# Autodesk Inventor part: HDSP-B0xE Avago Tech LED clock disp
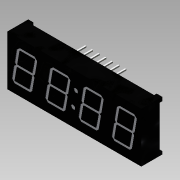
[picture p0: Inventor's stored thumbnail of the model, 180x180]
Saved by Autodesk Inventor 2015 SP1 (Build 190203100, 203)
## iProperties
Created: 2015-05
Part Number: HDSP-B0xE Avago Tech LED clock disp
Material: Thermoplastic Resin
Document SubType Name: Modeling
Designer: kazys
Density: 1.28 g/cm^3
Appearance: Black
Author: kazys
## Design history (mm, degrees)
sketch "Sketch1"
  geometry: L1 (-25.603, 9.55)-(25.603, 9.55); L2 (25.603, 9.55)-(25.603, -9.55); L3 (25.603, -9.55)-(-25.603, -9.55); L4 (-25.603, -9.55)-(-25.603, 9.55); L5 (-25.603, 9.55)-(25.603, -9.55); L6 (25.603, 9.55)-(-25.603, -9.55); 2 further points
  constraints: 12 end point, 2 midpoint, 2 parallel, 1 coincident, 1 horizontal, 1 perpendicular
  dimensions: "d0" = 51.2064 distance of L2.end L3.end; "d1" = 19.1008 distance of L1.end L2.end
extrude "Extrusion1" new body sketch "Sketch1" distance "d2" = 8.001; taper "d3" = 0 deg
sketch "Sketch2"
  geometry: L1 (25.603, 9.55)-(-25.603, 9.55) reference; L2 (-25.603, 9.55)-(-25.603, -9.55) reference; L3 (-25.603, -9.55)-(25.603, -9.55) reference; L4 (25.603, -9.55)-(25.603, 9.55) reference; L5 (-25.603, 9.55)-(-23.478, 9.55); L6 (-23.478, 9.55)-(-23.478, 8.086); L7 (-23.478, 8.086)-(-25.603, 8.086); L8 (-25.603, 8.086)-(-25.603, 9.55); L9 (-25.603, -9.55)-(-23.771, -9.55); L10 (-23.771, -9.55)-(-23.771, -8.392); L11 (-23.771, -8.392)-(-25.603, -8.392); L12 (-25.603, -8.392)-(-25.603, -9.55); L13 (25.603, -9.55)-(23.601, -9.55); L14 (23.601, -9.55)-(23.601, -8.392); L15 (23.601, -8.392)-(25.603, -8.392); L16 (25.603, -8.392)-(25.603, -9.55); L17 (25.603, 9.55)-(23.601, 9.55); L18 (23.601, 9.55)-(23.601, 8.086); L19 (23.601, 8.086)-(25.603, 8.086); L20 (25.603, 8.086)-(25.603, 9.55); 1 further point
  constraints: 32 end point, 8 parallel, 4 horizontal, 4 perpendicular, 3 point on line
extrude "Extrusion2" cut sketch "Sketch2" distance "d4" = 0.9906; taper "d5" = 0 deg
sketch "Sketch3"
  geometry: L1 (-7.874, 7.874)-(-7.366, 7.874); L2 (-7.366, 7.874)-(-7.366, 7.366); L3 (-7.366, 7.366)-(-7.874, 7.366); L4 (-7.874, 7.366)-(-7.874, 7.874); L5 (-7.62, 7.874)-(-7.366, 7.62); 1 further point
  constraints: 10 end point, 2 midpoint, 2 parallel, 1 horizontal, 1 perpendicular
  dimensions: "d6" = 0.508 distance of L2.end L3.end; "d7" = 0.508 distance of L1.end L2.end; "d8" = 7.62 horizontal distance of L5.start point (0, 0); "d9" = 7.62 vertical distance of L5.end point (0, 0)
extrude "Extrusion3" join sketch "Sketch3" distance "d10" = 4.9784 (computed from d4); taper "d11" = 0 deg
pattern_linear "Rectangular Pattern1" dims "d14" = 2.54, "d17" = 15.24
sketch "Sketch4"
  geometry: L1 (-19.05, 0)-(-19.05, -0.026); L2 (-21.816, 6.426)-(-14.018, 6.426); L3 (-16.284, -6.426)-(-24.082, -6.426); L4 (-22.433, 0)-(-15.667, 0); L5 (-15.229, 5.41)-(-20.963, 5.41); L6 (-22.871, -5.41)-(-17.137, -5.41); L7 (-22.007, -0.508)-(-16.272, -0.508); L8 (-15.241, -0.508)-(-15.151, -0.508); L9 (-22.949, 0.508)-(-22.859, 0.508); L10 (-21.828, 0.508)-(-16.093, 0.508); L11 (-23.903, -5.41)-(-23.05, -6.426); L12 (-16.105, -5.41)-(-17.137, -6.426); L13 (-14.197, 5.41)-(-15.198, 6.426); L14 (-21.995, 5.41)-(-20.784, 6.426); L15 (-15.062, 0.508)-(-15.667, 0); L16 (-15.241, -0.508)-(-15.667, 0); L17 (-23.038, -0.508)-(-22.433, 0); L18 (-22.859, 0.508)-(-22.433, 0); L19 (-14.197, 5.41)-(-15.062, 0.508); L20 (-15.241, -0.508)-(-16.105, -5.41); L21 (-24.082, -6.426)-(-23.038, -0.508); L22 (-22.859, 0.508)-(-21.816, 6.426); L23 (-20.963, 5.41)-(-21.828, 0.508); L24 (-22.007, -0.508)-(-22.871, -5.41); L25 (-17.137, -5.41)-(-16.272, -0.508); L26 (-16.093, 0.508)-(-15.229, 5.41); L27 (-17.917, 6.426)-(-20.183, -6.426); 5 further points
  constraints: 54 end point, 13 parallel, 10 point on line, 7 midpoint, 5 perpendicular, 1 horizontal, 1 horizontal alignment, 1 vertical
  dimensions: "d18" = 19.05 distance from line of point (0, 0) L1; "d21" = 7.7978 distance of L2.start L2.end; "d22" = 12.8524 distance between parallel lines of L3 L2; "d37" = 0.508 distance between parallel lines of L4 L7 (= 0.5 x d38); "d38" = 1.016 distance between parallel lines of L10 L7 (= d45); "d40" = 80 deg angle of L3 L27; "d41" = 1.016 distance between parallel lines of L24 L21; "d42" = 1.016 distance between parallel lines of L22 L23 (= d41); "d43" = 1.016 distance between parallel lines of L20 L25 (= d41); "d44" = 1.016 distance between parallel lines of L26 L19 (= d41); "d45" = 1.016 distance between parallel lines of L2 L5; "d46" = 1.016 distance between parallel lines of L3 L6 (= d45)
extrude "Extrusion4" cut sketch "Sketch4" distance "d26" = 0.254; taper "d27" = 0 deg
pattern_linear "Rectangular Pattern2" dims "d30" = 12.7
sketch "Sketch5"
  geometry: L1 (0.528, 2.997)-(-0.528, -2.997); L2 (-23.601, -9.55)-(23.771, -9.55) reference; C1 r 0.851 at (-0.528, -2.997); C2 r 0.851 at (0.528, 2.997); 2 further points
  constraints: 2 centre point, 2 end point, 1 coincident, 1 midpoint
  dimensions: "d31" = 1.7018 diameter of C2; "d32" = 1.7018 diameter of C1 (= d31); "d33" = 5.9944 vertical distance of L1.start L1.end; "d34" = 80 deg angle of L2 L1
extrude "Extrusion5" cut sketch "Sketch5" distance "d35" = 0.254; taper "d36" = 0 deg
body "Solid1"
node "Projected Loop1"
other parameters: "d19" = 100 deg, "d20" = 80 deg, "d23" = 1.016, "d24" = 1.016, "d25" = 0.508
